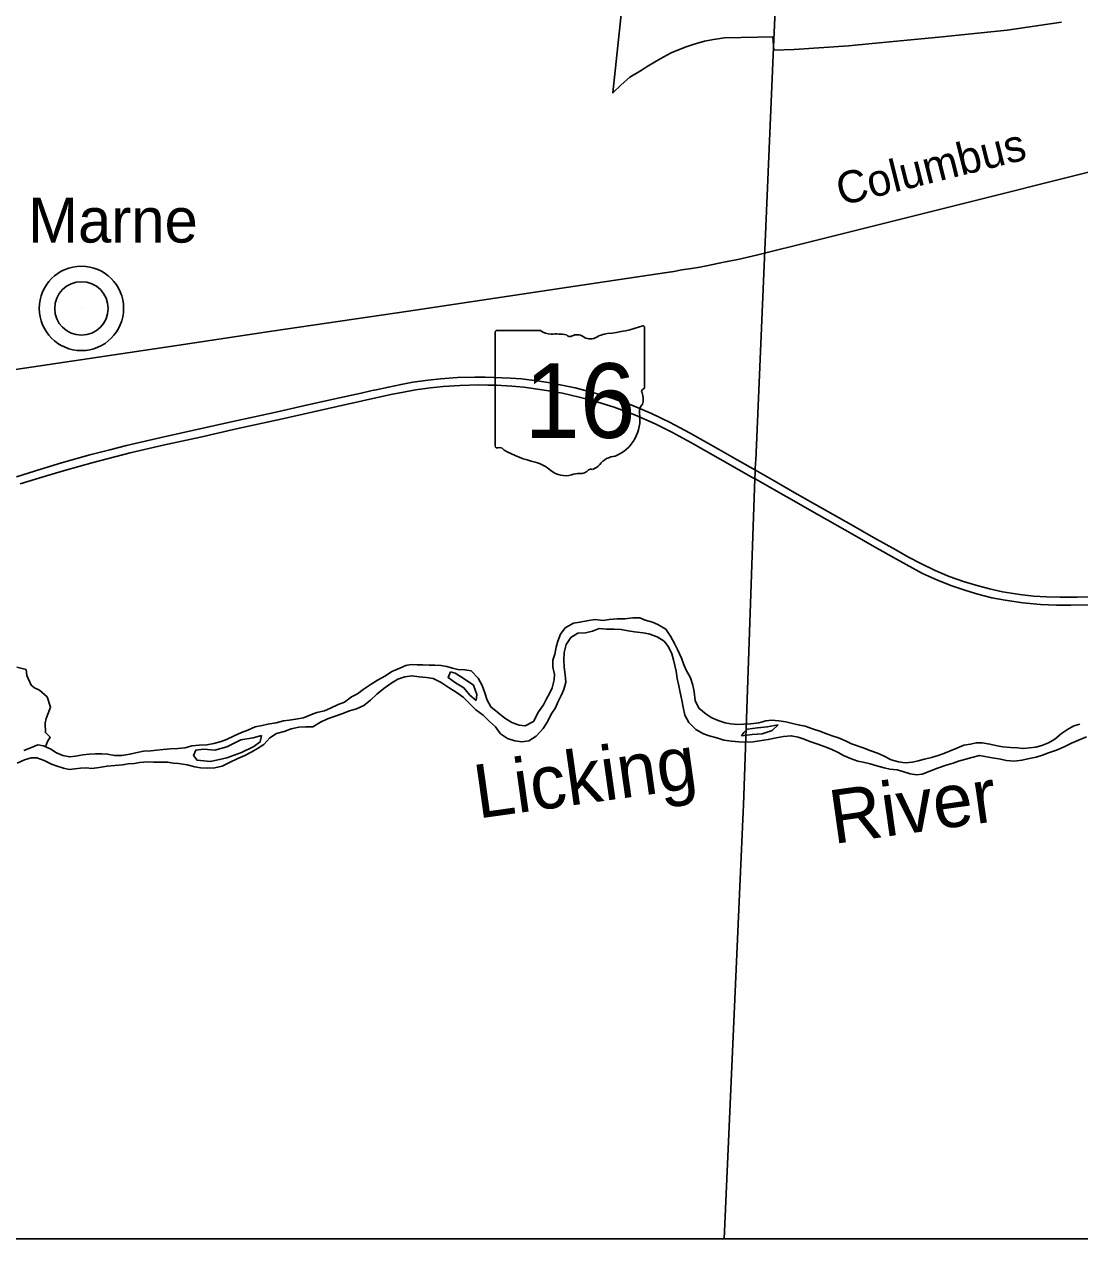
# Model space of a CAD drawing. Extents: x 0 to 34, y 0 to 22.
# Drawn here: x 5.204 to 8.347, y 13.067 to 16.684 of the extents above; entities that cross this region are included whole.
import ezdxf

# ---------------------------------------------------------------- set-up
doc = ezdxf.new("R2010")
doc.units = 0
for name, color, linetype in [('GM_X_Corporation', 7, 'Continuous'), ('GM_X_Major_River', 7, 'Continuous'), ('GM_X_Major_River_Text', 7, 'Continuous'), ('GM_X_Minor_River', 7, 'Continuous'), ('GM_X_Rail_Line', 7, 'Continuous'), ('GM_X_Rail_Line_Text', 7, 'Continuous'), ('GM_X_State_Route', 7, 'Continuous'), ('GM_X_State_Shield', 7, 'Continuous'), ('GM_X_Township', 7, 'Continuous'), ('GM_X_Unincorporated', 7, 'Continuous'), ('GM_X_Unincorporated_Location', 7, 'Continuous'), ('GM_X_Unincorporated_Text', 7, 'Continuous'), ('SH_Text', 7, 'Continuous')]:
    doc.layers.add(name, color=color, linetype=linetype)

msp = doc.modelspace()

# ---------------------------------------------------------------- linework, layer by layer
at = {"layer": 'GM_X_Corporation'}
msp.add_lwpolyline([(8.2925, 16.6899), (8.1306, 16.6664), (7.9269, 16.6455), (7.7285, 16.6272), (7.6579, 16.6194), (7.4961, 16.6089), (7.4356, 16.6065), (7.4332, 16.6462), (7.3876, 16.6456), (7.3392, 16.6444), (7.289, 16.6432), (7.2567, 16.6384), (7.2293, 16.6342), (7.1988, 16.6247), (7.1719, 16.6157), (7.1307, 16.599), (7.0978, 16.5808), (7.0638, 16.5613), (7.0387, 16.5458), (7.0076, 16.5267), (6.9813, 16.5034), (6.957, 16.4798), (6.988, 16.7792)], dxfattribs=at)
at = {"layer": 'GM_X_Major_River'}
for points in [[(8.3475, 14.5997), (8.3297, 14.5944), (8.3106, 14.5834), (8.2922, 14.5718), (8.2725, 14.5544), (8.2534, 14.544), (8.2336, 14.5362), (8.2158, 14.5315), (8.1973, 14.5288), (8.1787, 14.5274), (8.1615, 14.5286), (8.141, 14.5303), (8.1174, 14.5321), (8.1007, 14.5351), (8.0796, 14.5401), (8.0566, 14.5438), (8.038, 14.5436), (8.0214, 14.5403), (8.0017, 14.5369), (7.9806, 14.5285), (7.959, 14.5187), (7.9418, 14.5122), (7.9252, 14.5063), (7.9054, 14.4998), (7.885, 14.4951), (7.8653, 14.4899), (7.8487, 14.4865), (7.8269, 14.4844), (7.8071, 14.4875), (7.7853, 14.4937), (7.7629, 14.5051), (7.745, 14.5132), (7.7245, 14.5201), (7.702, 14.5289), (7.6674, 14.5414), (7.6514, 14.549), (7.629, 14.5591), (7.613, 14.564), (7.5957, 14.5697), (7.5726, 14.5784), (7.5514, 14.586), (7.5297, 14.5935), (7.513, 14.5965), (7.4919, 14.6015), (7.4714, 14.6065), (7.451, 14.6095), (7.4286, 14.6113), (7.412, 14.6092), (7.3909, 14.6033), (7.3679, 14.6006), (7.3456, 14.5991), (7.329, 14.5983), (7.3072, 14.6001), (7.2912, 14.6032), (7.2701, 14.6107), (7.2509, 14.6182), (7.2348, 14.629), (7.213, 14.6473), (7.2019, 14.6703), (7.1986, 14.6959), (7.1952, 14.7157), (7.1874, 14.7373), (7.1744, 14.7622), (7.1667, 14.7788), (7.1608, 14.796), (7.1491, 14.8215), (7.1407, 14.8393), (7.1284, 14.8616), (7.1148, 14.882), (7.091, 14.8965), (7.0744, 14.9034), (7.0532, 14.9097), (7.0372, 14.9159), (7.0161, 14.9158), (6.9919, 14.913), (6.9695, 14.9129), (6.9453, 14.9108), (6.9274, 14.9087), (6.9044, 14.9111), (6.8795, 14.9077), (6.8584, 14.9037), (6.8393, 14.9003), (6.8144, 14.8861), (6.8005, 14.8674), (6.7924, 14.8463), (6.788, 14.829), (6.7837, 14.8085), (6.7781, 14.7905), (6.7782, 14.7694), (6.7828, 14.7477), (6.7823, 14.7311), (6.7755, 14.708), (6.7685, 14.6913)], [(5.1834, 14.4835), (5.2044, 14.4932), (5.2248, 14.4991), (5.2421, 14.4993), (5.2632, 14.4918), (5.285, 14.4804), (5.3023, 14.4741), (5.3215, 14.4685), (5.3382, 14.4648), (5.3548, 14.4669), (5.372, 14.4689), (5.3886, 14.469), (5.4052, 14.4673), (5.4269, 14.4706), (5.4506, 14.4746), (5.4742, 14.4767), (5.4965, 14.4782), (5.5138, 14.4809), (5.5317, 14.4823), (5.5482, 14.4856), (5.5719, 14.4871), (5.5885, 14.4866), (5.6083, 14.4867), (5.6313, 14.4863), (5.6473, 14.4838), (5.6633, 14.482), (5.6895, 14.4784), (5.7119, 14.4728), (5.7292, 14.4697), (5.7509, 14.468), (5.7714, 14.4694), (5.7931, 14.4741), (5.8154, 14.4851), (5.8396, 14.4968), (5.8606, 14.5059), (5.8816, 14.5176), (5.8988, 14.5267), (5.9178, 14.539), (5.9356, 14.5589), (5.9553, 14.5719), (5.9776, 14.5778), (5.9987, 14.5856), (6.0216, 14.5903), (6.0421, 14.5917), (6.0632, 14.5919), (6.0861, 14.6055), (6.1071, 14.6152), (6.1294, 14.6237), (6.1498, 14.6303), (6.1721, 14.6388), (6.1938, 14.6447), (6.2148, 14.6551), (6.2351, 14.6706), (6.2542, 14.6893), (6.2745, 14.7061), (6.2961, 14.7203), (6.3165, 14.7333), (6.3375, 14.7405), (6.3586, 14.7438), (6.3803, 14.7401), (6.4021, 14.739), (6.4212, 14.736), (6.445, 14.7234), (6.4694, 14.7082), (6.4899, 14.6949), (6.5105, 14.6797), (6.5323, 14.6594), (6.5491, 14.6423), (6.5703, 14.6265), (6.5889, 14.6087), (6.607, 14.5916), (6.6218, 14.5712), (6.643, 14.5567), (6.6648, 14.5498), (6.6852, 14.5474), (6.7063, 14.5501), (6.7279, 14.5637), (6.7489, 14.5869), (6.7628, 14.6081), (6.7735, 14.6293), (6.7855, 14.6486), (6.793, 14.6646), (6.8037, 14.6864), (6.8106, 14.7025), (6.8162, 14.7249), (6.8148, 14.7467), (6.8121, 14.769), (6.8106, 14.7914), (6.8118, 14.8132), (6.818, 14.8369), (6.8319, 14.8574), (6.8522, 14.8704), (6.8752, 14.8718), (6.8963, 14.8765), (6.916, 14.8843), (6.9378, 14.8826)], [(6.9378, 14.8826), (6.9602, 14.8821), (6.9812, 14.881), (7.0024, 14.8779), (7.0216, 14.8749), (7.0471, 14.8712), (7.0638, 14.8682), (7.0888, 14.86), (7.1093, 14.8468), (7.1222, 14.8302), (7.1326, 14.8086), (7.1372, 14.7913), (7.1411, 14.7741), (7.1451, 14.7575), (7.1484, 14.7351), (7.1531, 14.7134), (7.157, 14.6936), (7.1623, 14.6713), (7.1657, 14.6502), (7.1709, 14.6266), (7.1826, 14.6049), (7.2038, 14.584), (7.2263, 14.5707), (7.2436, 14.5651), (7.266, 14.5588), (7.2871, 14.552), (7.3102, 14.5489), (7.3319, 14.5472), (7.353, 14.5461), (7.3741, 14.5469), (7.3932, 14.5496), (7.4194, 14.5536), (7.443, 14.5589), (7.4647, 14.5623), (7.4877, 14.565), (7.5082, 14.5607), (7.5261, 14.5544), (7.5434, 14.5475), (7.5639, 14.5413), (7.5889, 14.5325), (7.6062, 14.525), (7.6274, 14.5149), (7.6434, 14.5061), (7.6645, 14.4973), (7.6863, 14.4898), (7.7023, 14.4861), (7.7228, 14.4811), (7.7427, 14.4755), (7.7644, 14.4693), (7.7811, 14.4655), (7.8035, 14.4632), (7.8201, 14.4588), (7.8419, 14.4519), (7.8611, 14.4489), (7.8777, 14.4509), (7.9, 14.4594), (7.9229, 14.4685), (7.9491, 14.4777), (7.9695, 14.4836), (7.986, 14.4889), (8.0077, 14.4954), (8.0256, 14.5007), (8.0485, 14.5066), (8.0645, 14.5035), (8.0863, 14.4992), (8.1061, 14.4962), (8.1285, 14.4912), (8.1528, 14.4895), (8.1745, 14.4922), (8.1968, 14.4969), (8.2173, 14.5008), (8.2364, 14.5074), (8.2542, 14.5139), (8.2778, 14.5224), (8.3001, 14.5322), (8.3224, 14.5432), (8.3434, 14.5517), (8.367, 14.5621)], [(6.7685, 14.6913), (6.7591, 14.6746), (6.7503, 14.6573), (6.7351, 14.636), (6.7206, 14.6078), (6.6958, 14.5948), (6.6779, 14.5966), (6.6554, 14.6047), (6.6349, 14.6174), (6.6143, 14.6338), (6.5931, 14.6509), (6.5821, 14.6713), (6.5756, 14.693), (6.5671, 14.7147), (6.5561, 14.737), (6.5348, 14.7579), (6.5163, 14.761), (6.4952, 14.7628), (6.4792, 14.7665), (6.4625, 14.7715), (6.4446, 14.7745), (6.4267, 14.775), (6.4095, 14.7755), (6.3909, 14.7767), (6.3743, 14.7766), (6.3564, 14.7777), (6.3398, 14.7744), (6.322, 14.7666), (6.2984, 14.7568), (6.2793, 14.7438), (6.2564, 14.7309), (6.2367, 14.7186), (6.2132, 14.7024), (6.196, 14.6895), (6.1788, 14.681), (6.1572, 14.6655), (6.1387, 14.6577), (6.1158, 14.6473), (6.098, 14.6395), (6.0756, 14.6342), (6.0591, 14.6283), (6.0355, 14.6185), (6.0132, 14.6145), (5.9934, 14.6112), (5.9761, 14.6091), (5.9538, 14.6038), (5.9295, 14.5998), (5.9123, 14.5959), (5.8913, 14.5919), (5.8703, 14.5815), (5.8511, 14.5749), (5.8288, 14.5652), (5.8065, 14.5541), (5.79, 14.5476), (5.7683, 14.5417), (5.7479, 14.5383), (5.7249, 14.5369), (5.7032, 14.5354), (5.6828, 14.5295), (5.6617, 14.5274), (5.64, 14.526), (5.6176, 14.5245), (5.5985, 14.5225), (5.5812, 14.5204), (5.5595, 14.519), (5.5404, 14.515), (5.5187, 14.5097), (5.4951, 14.5063), (5.4733, 14.5062), (5.4522, 14.5105), (5.4356, 14.511), (5.4164, 14.5108), (5.3973, 14.5101), (5.3781, 14.508), (5.3564, 14.5046), (5.3398, 14.5019), (5.3193, 14.5063), (5.3001, 14.5144), (5.2828, 14.5252), (5.261, 14.5352), (5.245, 14.5377), (5.2208, 14.5279), (5.2029, 14.5214)], [(6.4735, 14.7556), (6.466, 14.7382), (6.4878, 14.723), (6.5128, 14.7073), (6.5309, 14.6856), (6.5495, 14.6704)], [(6.5495, 14.6704), (6.5513, 14.6877), (6.5415, 14.7158), (6.5113, 14.7367), (6.487, 14.7512), (6.4735, 14.7556)], [(7.3401, 14.5645), (7.3714, 14.5686), (7.4014, 14.5708), (7.4314, 14.5806), (7.4485, 14.598)], [(7.4485, 14.598), (7.4166, 14.5913), (7.3872, 14.5886), (7.3572, 14.5845), (7.347, 14.5748), (7.3401, 14.5645)], [(5.7078, 14.506), (5.7188, 14.492), (5.7585, 14.4879), (5.8069, 14.4997), (5.8509, 14.5148), (5.8879, 14.533), (5.9063, 14.5466), (5.9106, 14.5658)], [(5.9106, 14.5658), (5.8858, 14.5586), (5.8494, 14.5532), (5.8073, 14.5324), (5.7716, 14.5225), (5.7384, 14.5248), (5.7148, 14.5221), (5.7078, 14.506)]]:
    msp.add_lwpolyline(points, dxfattribs=at)
at = {"layer": 'GM_X_Minor_River'}
msp.add_lwpolyline([(5.267, 14.5324), (5.2731, 14.5483), (5.2814, 14.5605), (5.2673, 14.5745), (5.2667, 14.6027), (5.2692, 14.6161), (5.2826, 14.6501), (5.2723, 14.6808), (5.2492, 14.7006), (5.2345, 14.7082), (5.2249, 14.7153), (5.2115, 14.7441), (5.2095, 14.762), (5.182, 14.7696)], dxfattribs=at)
at = {"layer": 'GM_X_Rail_Line'}
msp.add_lwpolyline([(5.0164, 15.6318), (5.278, 15.6709), (5.6586, 15.7275), (5.9413, 15.7696), (6.3478, 15.83), (6.8245, 15.9012), (7.1102, 15.944), (7.1383, 15.9481), (7.1623, 15.9522), (7.1909, 15.9568), (7.2159, 15.9611), (7.2408, 15.9659), (7.2681, 15.9714), (7.2974, 15.9774), (7.3283, 15.9838), (7.3848, 15.9966), (7.5519, 16.0385), (7.7986, 16.1001), (8.0719, 16.1683), (8.2939, 16.2241), (8.5635, 16.291)], dxfattribs=at)
at = {"layer": 'GM_X_State_Route'}
for points in [[(5.1815, 15.3363), (5.2531, 15.3589), (5.3149, 15.3775), (5.3999, 15.4012), (5.4593, 15.4168), (5.5087, 15.4292), (5.6116, 15.4529), (5.7274, 15.4787), (5.8389, 15.5036), (5.9494, 15.5281), (6.0352, 15.5472), (6.1284, 15.5683), (6.2074, 15.5857), (6.2404, 15.593), (6.2522, 15.5956), (6.2883, 15.6036), (6.3261, 15.6116), (6.3613, 15.6177), (6.4063, 15.6241), (6.4437, 15.6281), (6.4944, 15.6316), (6.5462, 15.6332), (6.5762, 15.6333), (6.6027, 15.6325), (6.6515, 15.63), (6.6843, 15.6279)], [(6.6843, 15.6279), (6.7385, 15.621), (6.7697, 15.6162), (6.7994, 15.6106), (6.8446, 15.6009), (6.8931, 15.5886), (6.9538, 15.5703), (7.0132, 15.5492), (7.0718, 15.5249), (7.1276, 15.4982), (7.1848, 15.4675), (7.2708, 15.4188), (7.3266, 15.3871), (7.3811, 15.356), (7.4371, 15.3241), (7.492, 15.2928), (7.5583, 15.2551), (7.6123, 15.2244), (7.6672, 15.1935), (7.733, 15.1557), (7.7993, 15.1184), (7.837, 15.0971), (7.8737, 15.0776), (7.9166, 15.0567), (7.958, 15.0394), (8.0008, 15.0243), (8.0371, 15.0131), (8.0778, 15.0023), (8.1166, 14.9941), (8.1684, 14.9857), (8.2088, 14.9811), (8.2482, 14.9788), (8.2888, 14.9778), (8.3265, 14.978), (8.3393, 14.978), (8.4402, 14.9783)], [(5.192, 15.315), (5.2601, 15.3363), (5.3241, 15.3554), (5.4094, 15.3793), (5.5191, 15.4076), (5.618, 15.4301), (5.7287, 15.4548), (5.84, 15.4798), (5.964, 15.5072), (6.1363, 15.5459), (6.296, 15.5811), (6.3334, 15.5886), (6.3691, 15.5951), (6.4133, 15.6009), (6.451, 15.6049), (6.501, 15.6086), (6.5578, 15.6097), (6.5844, 15.6095), (6.6103, 15.6088), (6.6557, 15.6061), (6.692, 15.6032)], [(6.692, 15.6032), (6.7467, 15.5956), (6.7784, 15.5905), (6.8064, 15.5851), (6.8564, 15.5739), (6.8991, 15.5625), (6.9601, 15.5434), (7.0243, 15.5194), (7.0826, 15.4939), (7.1339, 15.4685), (7.1889, 15.4382), (7.276, 15.3889), (7.3758, 15.3325)], [(7.3758, 15.3325), (7.3802, 15.33), (7.4727, 15.2771), (7.572, 15.2209), (7.6699, 15.1651), (7.7358, 15.1275), (7.8009, 15.0907), (7.8787, 15.0486), (7.9233, 15.0285), (7.9662, 15.0115), (8.0076, 14.9972), (8.0433, 14.9865), (8.0854, 14.9762), (8.125, 14.9684), (8.177, 14.9604), (8.2303, 14.9561), (8.2779, 14.9542), (8.2813, 14.9542)], [(8.2813, 14.9542), (8.32, 14.9541), (8.4465, 14.9545)]]:
    msp.add_lwpolyline(points, dxfattribs=at)
at = {"layer": 'GM_X_State_Shield'}
for p, q in [((6.741, 15.7718), (6.6107, 15.7718)), ((7.0513, 15.6035), (7.0513, 15.7802)), ((6.6063, 15.766), (6.6063, 15.4283)), ((7.0512, 15.6036), (7.0513, 15.6035))]:
    msp.add_line(p, q, dxfattribs=at)
for centre, radius, start, end in [((6.6114, 15.7667), 0.00515, 98.1301, 188.1301), ((6.772, 15.811), 0.05, 231.6195, 271.1119), ((6.8928, 16.2322), 0.4719, 275.8445, 288.9065), ((7.0463, 15.7809), 0.00495, 351.8621, 97.738), ((6.7886, 15.5822), 0.1795, 80.4867, 94.9883), ((6.8294, 15.7685), 0.0144, 219.7921, 297.1024), ((6.8505, 15.7295), 0.03, 54.4667, 119.1411), ((6.8892, 15.783), 0.0361, 233.8562, 294.8282), ((6.953, 15.6687), 0.0949, 97.3462, 120.7689), ((7.0501, 15.5906), 0.00767, 107.944, 210.337), ((7.046, 15.6029), 0.0053, 289.6038, 7.7341), ((7.0014, 15.5682), 0.046, 340.033, 23.6496), ((6.9192, 15.5071), 0.118, 292.3089, 8.9858), ((7.069, 15.5296), 0.0335, 136.8065, 186.9296), ((6.6115, 15.4276), 0.0052, 171.9584, 258.3066), ((6.6123, 15.4621), 0.0397, 267.339, 280.6039), ((6.6204, 15.4088), 0.0143, 29.7484, 93.2717), ((6.801, 15.7122), 0.3407, 240.4129, 257.1985), ((6.6995, 15.2766), 0.1066, 47.1842, 75.836), ((6.8871, 15.3956), 0.0381, 282.8732, 323.2771), ((6.969, 15.3335), 0.0646, 94.4031, 142.5768), ((6.8148, 15.4072), 0.0677, 230.7004, 286.2918), ((6.8538, 15.2904), 0.0556, 85.6951, 111.2099), ((6.8588, 15.3819), 0.036, 268.777, 315.5493), ((6.8914, 15.3492), 0.0101, 65.7517, 132.6484)]:
    msp.add_arc(centre, radius, start, end, dxfattribs=at)
at = {"layer": 'GM_X_Township'}
msp.add_lwpolyline([(7.2878, 13.067), (7.3449, 14.3381), (7.3457, 14.3583), (7.3798, 15.3309), (7.3804, 15.3492), (7.3808, 15.3569), (7.3817, 15.3787), (7.3819, 15.3847), (7.4355, 16.6384), (7.5303, 18.6845), (7.5438, 18.9496), (8.5619, 18.9174), (10.8875, 18.8291), (12.1312, 18.787), (15.1269, 18.7101), (15.5418, 18.6967), (15.9755, 18.686)], dxfattribs=at)
at = {"layer": 'GM_X_Unincorporated'}
for radius in [0.1256, 0.0796]:
    msp.add_circle((5.3744, 15.8378), radius, dxfattribs=at)
at = {"layer": 'GM_X_Unincorporated_Location'}
msp.add_line((5.3744, 15.8378), (5.3744, 15.8378), dxfattribs=at)
at = {"layer": 'SH_Text'}
msp.add_lwpolyline([(1.9289, 20.907), (19.068, 20.907), (19.068, 13.067), (1.9289, 13.067)], close=True, dxfattribs=at)

# ---------------------------------------------------------------- texts
at = {"layer": 'GM_X_Major_River_Text'}
for s, rotation, p in [('Licking', 8.0011, (6.5554, 14.3181)), ('River', 8.0022, (7.6136, 14.2424))]:
    msp.add_text(s, height=0.1598, rotation=rotation, dxfattribs=at).set_placement(p)
at = {"layer": 'GM_X_Rail_Line_Text'}
msp.add_text('Columbus', height=0.09556, rotation=14.0362, dxfattribs=at).set_placement((7.6357, 16.1434))
at = {"layer": 'GM_X_State_Shield'}
msp.add_text('16', height=0.22247, dxfattribs=at).set_placement((6.6933, 15.4521))
at = {"layer": 'GM_X_Unincorporated_Text'}
msp.add_text('Marne', height=0.13327, rotation=0, dxfattribs=at).set_placement((5.2159, 16.0339))

doc.saveas('drawing.dxf')
